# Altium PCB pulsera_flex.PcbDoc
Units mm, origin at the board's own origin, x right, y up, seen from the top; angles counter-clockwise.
Board outline 66.17 x 33.66 mm, 2 copper layers (Top Layer, Bottom Layer); 22 components, 13 nets, 52 pads, 0 vias.
Unrouted connection lines stored in the file: 4.
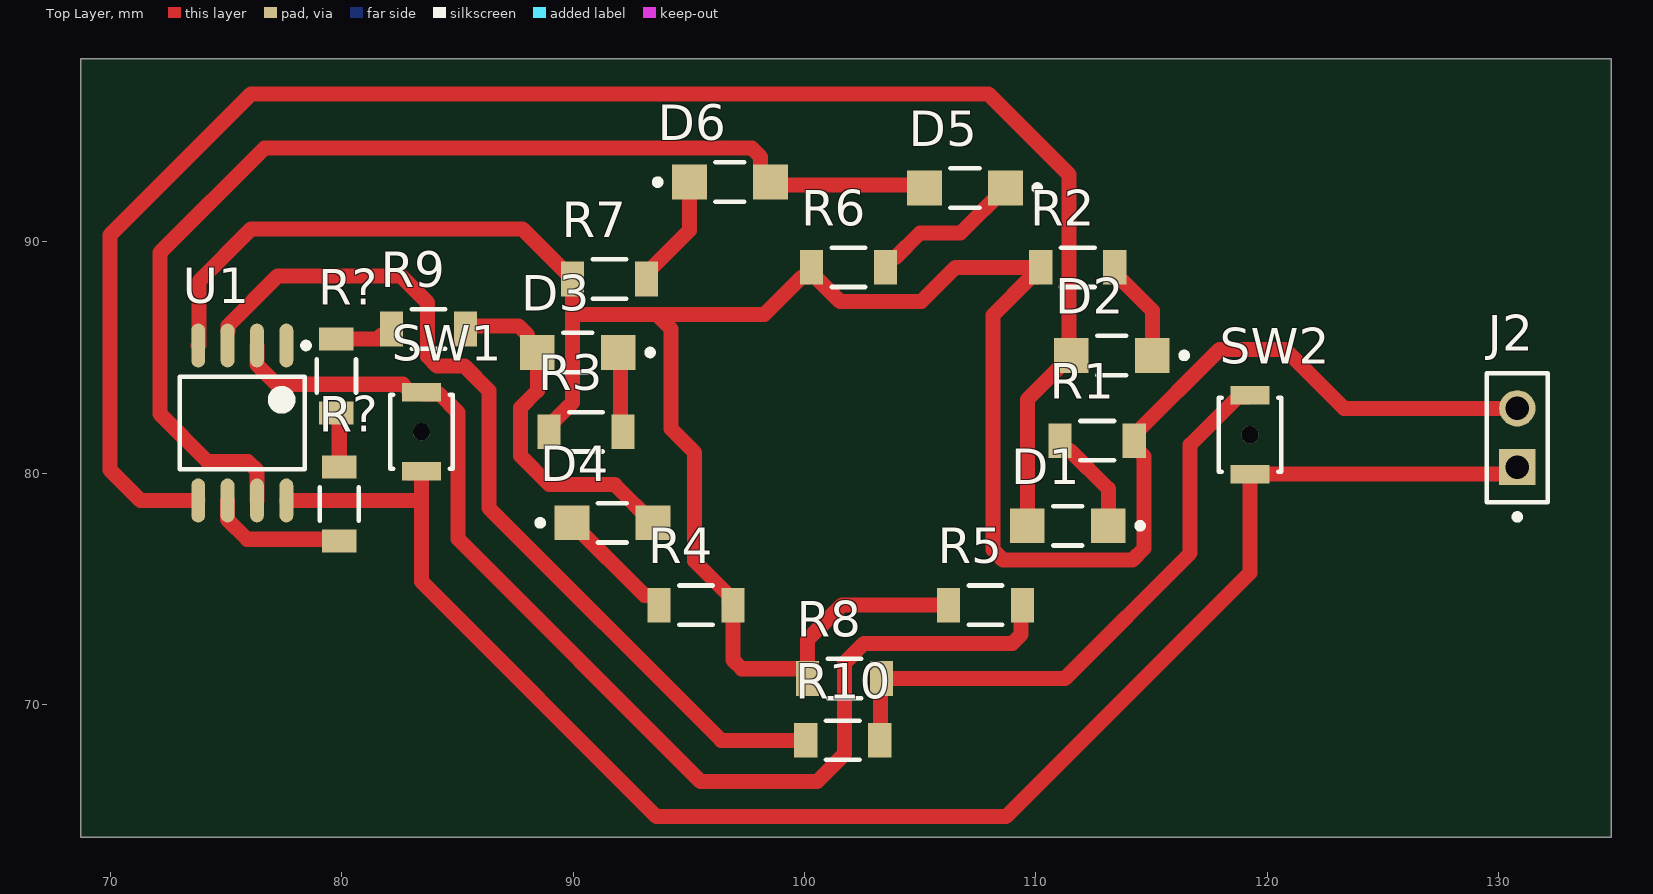
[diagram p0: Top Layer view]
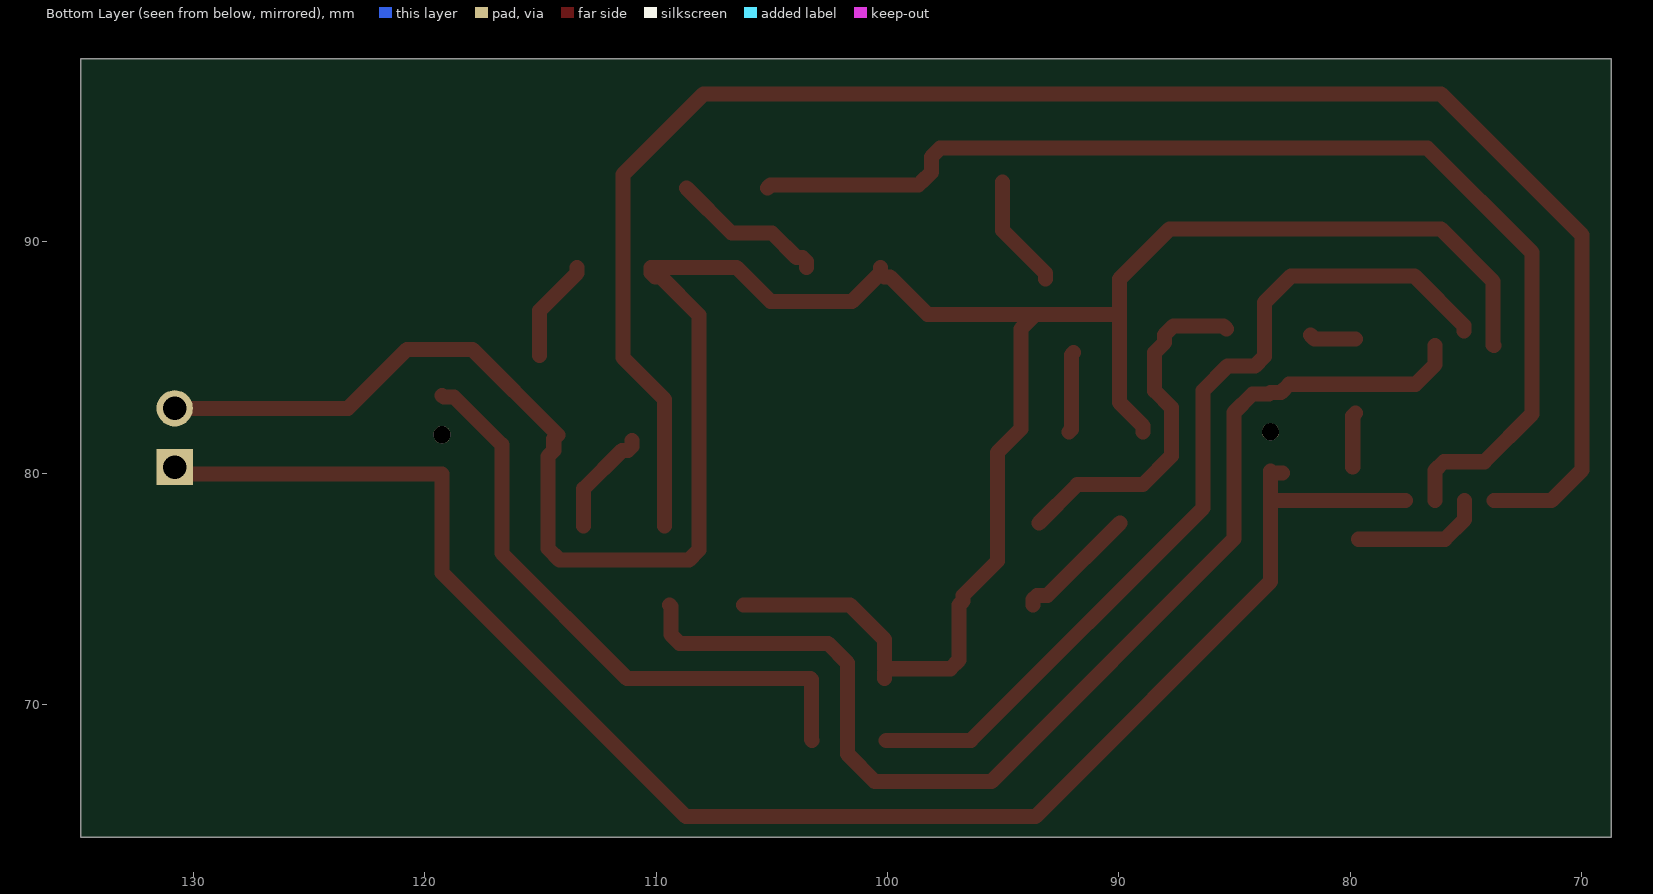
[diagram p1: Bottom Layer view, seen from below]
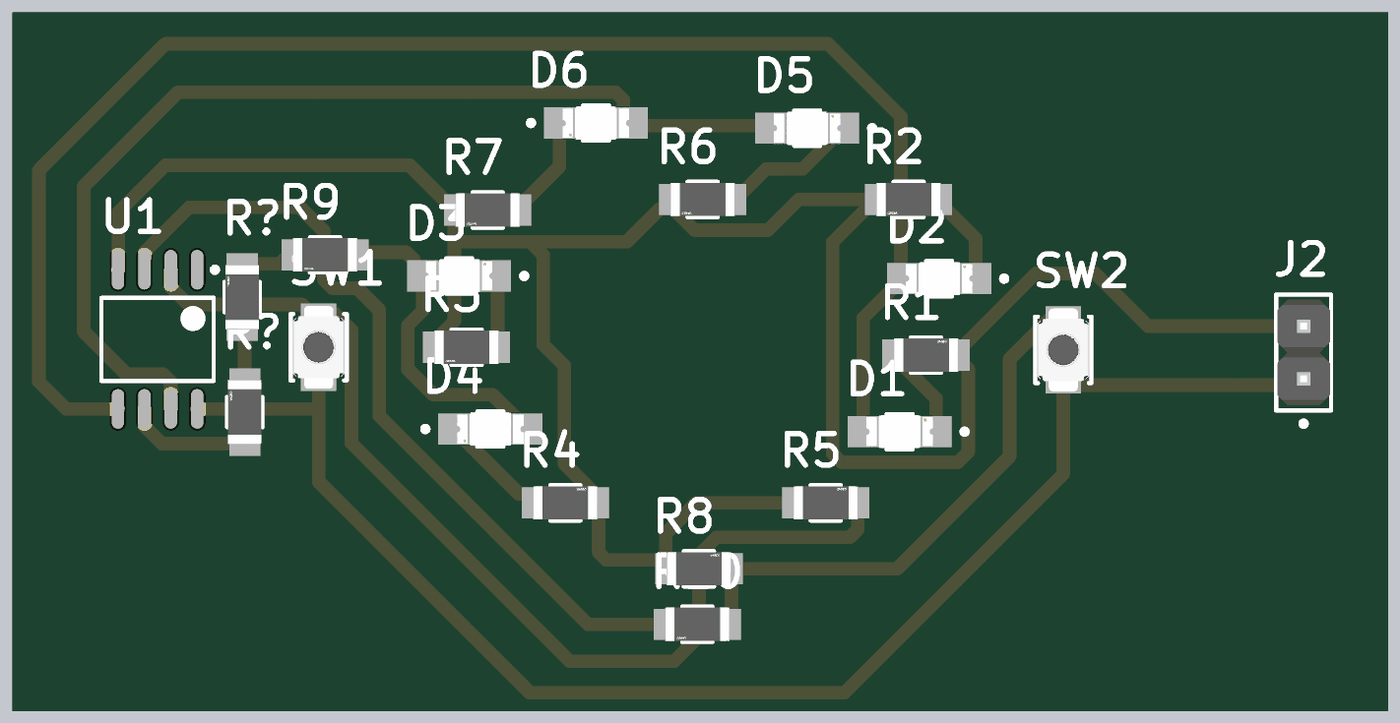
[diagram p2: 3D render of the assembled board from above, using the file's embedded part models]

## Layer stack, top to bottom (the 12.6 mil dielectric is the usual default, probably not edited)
Top Solder: solder mask 0.0102, Solder Resist, Dk 3.5
Top Layer: signal copper 0.0356
Dielectric 1: dielectric 0.32, FR-4, Dk 4.8
Bottom Layer: signal copper 0.0356
Bottom Solder: solder mask 0.0102, Solder Resist, Dk 3.5

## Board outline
68.707,64.262 134.874,64.262 134.874,97.917 68.707,97.917

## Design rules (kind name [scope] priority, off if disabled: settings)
Clearance [All] p1: gap=0.4 ignorepadtopadclearanceinfootprint=FALSE
PolygonConnect [All] p1: connectstyle=Relief reliefconductorwidth=0.254 reliefentries=4 polygonreliefangle="90 Angle" airgapwidth=0.254
RoutingVias [All] p1: holewidth=0.711 width=1.27 viastyle="Through Hole" minholewidth=0.711 minwidth=1.27 maxholewidth=0.711 maxwidth=1.27
SolderMaskExpansion [All] p1: expansion=0.102 istentingtop=FALSE
SupplyNets "Schematic Supply Nets_1" [InNet('GND')] p1: voltage=0.000
SupplyNets "Schematic Supply Nets" [InNet('VCC')] p2: voltage=0.000
Width [All] p1: maxlimit=0.65 minlimit=0.65 preferedwidth=0.65 minimp=50.000000 maximp=50.000000 favimp=50.000000
30 further rules are at their usual default settings.

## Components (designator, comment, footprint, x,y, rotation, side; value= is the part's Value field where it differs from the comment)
D1 "HSMS-C150" FP-HSMS-C150-MFG 111.379,77.724 r180 top
D2 "HSMS-C150" FP-HSMS-C150-MFG 113.284,85.09 r180 top
D3 "HSMS-C150" FP-HSMS-C150-MFG 90.198,85.217 r180 top
D4 "HSMS-C150" FP-HSMS-C150-MFG 91.694,77.851 r0 top
D5 "HSMS-C150" FP-HSMS-C150-MFG 106.934,92.329 r180 top
D6 "HSMS-C150" FP-HSMS-C150-MFG 96.774,92.583 r0 top
J2 "M20-9990246" FP-M20-9990246-MFG 130.81,81.534 r90 top
R1 "RC1206JR-070RL" FP-RC1206-MFG 112.649,81.407 r0 top value=0Ω
R2 "RC1206JR-070RL" FP-RC1206-MFG 111.811,88.9 r180 top value=0Ω
R3 "RC1206JR-070RL" FP-RC1206-MFG 90.551,81.788 r180 top value=0Ω
R4 "RC1206JR-070RL" FP-RC1206-MFG 95.301,74.295 r0 top value=0Ω
R5 "RC1206JR-070RL" FP-RC1206-MFG 107.823,74.295 r0 top value=0Ω
R6 "RC1206JR-070RL" FP-RC1206-MFG 101.905,88.9 r180 top value=0Ω
R7 "RC1206JR-070RL" FP-RC1206-MFG 91.567,88.392 r180 top value=0Ω
R8 "RC1206JR-070RL" FP-RC1206-MFG 101.727,71.12 r0 top value=0Ω
R9 "RC1206JR-070RL" FP-RC1206-MFG 83.744,86.233 r180 top value=0Ω
R10 "RC1206JR-070RL" FP-RC1206-MFG 101.651,68.453 r180 top value=0Ω
R? "RC1206JR-070RL" FP-RC1206-MFG 79.756,84.201 r90 top value=0Ω
R? "RC1206JR-070RL" FP-RC1206-MFG 79.883,78.664 r90 top value=0Ω
SW1 "B3U-1000P-B" FP-B3U-1000P-B-MFG 83.439,81.788 r90 top
SW2 "B3U-1000P-B" FP-B3U-1000P-B-MFG 119.253,81.661 r90 top
U1 "ATtiny45-20SUR" 8S2_L 75.692,82.169 r270 top

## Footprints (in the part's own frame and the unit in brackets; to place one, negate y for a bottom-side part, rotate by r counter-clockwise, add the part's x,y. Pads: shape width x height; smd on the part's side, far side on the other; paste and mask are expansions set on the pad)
8S2_L [mm] "SOP, 8-Leads, Body 5.3x5.3mm, Pitch 1.27mm, IPC High Density"
  oval 1.9x0.6 smd: 1(-3.35,1.905) 2(-3.35,0.635) 3(-3.35,-0.635) 4(-3.35,-1.905) 5(3.35,-1.905) 6(3.35,-0.635) 7(3.35,0.635) 8(3.35,1.905)
  silkscreen extent -3.47,-2.7 2,2.88, body extent -2.7,-2.68 2.7,2.68, height 2.16
FP-B3U-1000P-B-MFG [mm]
  rect 0.8x1.7 smd paste+0 mask+0: 1(-1.7,0) 2(1.7,0)
  round 0.75 hole 0.75 unplated paste-2539.97 mask+0: ""(0,0)
  silkscreen extent -1.6,-1.35 1.6,1.35, body extent -2.2,-1.45 2.2,1.45, height 0.25
FP-HSMS-C150-MFG [mm]
  rect 1.5x1.5 smd paste+0 mask+0: 1(-1.75,0) 2(1.75,0)
  silkscreen extent -3.25,-0.85 0.63,0.85, body extent -2.6,-0.95 2.6,0.95, height 0.25
FP-M20-9990246-MFG [mm]
  rect 1.57x1.57 hole 1.02 paste-2539.97 mask+0: 1(-1.27,0)
  round 1.57 hole 1.02 paste-2539.97 mask+0: 2(1.27,0)
  silkscreen extent -3.55,-1.32 2.79,1.32, body extent -2.89,-1.42 2.89,1.42, height 0.25
FP-RC1206-MFG [mm]
  rect 1x1.5 smd paste+0 mask+0: 1(-1.6,0) 2(1.6,0)
  silkscreen extent -0.72,-0.85 0.72,0.85, body extent -2.2,-0.95 2.2,0.95, height 0.25

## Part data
D1 D2 D3 D4 D5 D6: library part CMP-21615-000001-1, "LED RED DIFFUSED CHIP SMD", Case Code (Imperial)=1206, Case Code (Metric)=3216, Color=Red, Forward Current=20mA, Forward Voltage=2.1V, Lens Color=White, Max Operating Temperature=85°C, Min Operating Temperature=-40°C, Package Quantity=1, Power Dissipation=65mW, Reverse Voltage=5V
J2: library part CMP-15831-000009-1, "CONN HEADER VERT 2POS 2.54MM", Current Rating=3A, Manufacturer=Harwin, Temperature="-40°C to +105°C", Temperature Range High=+105°C, Temperature Range Low=-40°C
R1 R2 R3 R4 R5 R6 R7 R8 R9 R10 R? R?: library part CMP-2100-03681-2, "RES SMD 0 OHM JUMPER 1/4W 1206", Manufacturer=YAGEO, Package=RC1206, Power Rating=0.25W, Resistance=0Ω, Temperature="-55°C to +155°C", Temperature Coefficient=300ppm/°C, Temperature Range High=+155°C, Temperature Range Low=-55°C, Tolerance=5%, Voltage Rating=200V
SW1 SW2: library part CMP-08834-000005-1, "SWITCH TACTILE SPST-NO 0.05A 12V", Ambient Temperature Range High=+70°C, Ambient Temperature Range Low=-25°C, Contact Current Rating=50mA, Contact Resistance=100mΩ, Manufacturer=Omron, Operating Force=1.5N, Package=0, Temperature="-25°C to +70°C", Voltage Rating Dc=12V
U1: library part CMP-0093-00355-1, "8-bit AVR Microcontroller, 20MHz, 2.7-5.5V, 4K Flash, 256 Bytes EEPROM, 256 Bytes SRAM, Industrial Grade (-40°C to 85°C), 8-Lead SOIC, Pb-Free, Reel"

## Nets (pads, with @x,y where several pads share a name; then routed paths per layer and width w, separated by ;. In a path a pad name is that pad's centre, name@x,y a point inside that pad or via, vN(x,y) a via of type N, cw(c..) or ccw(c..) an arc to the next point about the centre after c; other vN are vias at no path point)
BOTON1: R5.2 SW1.2 U1.2 | length 50.8
  Top Layer w0.65: U1.2 76.327,84.689 77.172,83.844 82.633,83.844 82.989,83.488 SW1.2 83.514,83.413 84.227,83.413 85.014,82.626 85.014,77.165 95.504,66.675 100.548,66.675 101.727,67.854 101.727,71.795 102.574,72.643 108.985,72.643 109.366,73.024 109.366,74.238 R5.2
BOTON2: R8.2 R10.1 R10.2 SW2.2 U1.3 | length 65.2
  Top Layer w0.65: U1.3@75.082,86.144 75.082,86.385 77.216,88.519 82.55,88.519 83.693,87.376 83.693,85.05 84.112,84.631 85.295,84.631 86.36,83.566 86.36,78.486 96.393,68.453 R10.2 ; R10.1 103.289,68.491 103.289,71.082 R8.2 111.252,71.12 116.671,76.539 116.671,81.229 118.728,83.286 119.178,83.286 SW2.2
GND: J2.2 R1.2 R2.2 R3.2 R4.2 R5.1 R6.2 R7.2 R8.1 U1.4 | length 122.5
  Top Layer w0.65: U1.4 73.812,85.544 73.812,88.29 76.073,90.551 87.808,90.551 R7.2 89.967,86.868 ; R3.2 88.951,82.038 89.967,83.054 89.967,86.868 ; R8.1 100.127,71.37 99.952,71.545 97.282,71.545 96.901,71.926 R4.2 96.726,74.47 96.726,74.72 95.25,76.196 95.25,80.899 94.234,81.915 94.234,86.233 93.599,86.868 ; R8.1@100.127,71.545 100.127,72.812 101.613,74.298 106.048,74.298 106.051,74.295 R5.1 ; R6.2 R6.2@100.305,88.65 ; J2.2 123.317,82.804 120.777,85.344 117.936,85.344 114.249,81.657 114.424,81.482 114.424,80.982 114.681,80.725 114.681,76.751 114.179,76.249 108.579,76.249 108.154,76.674 108.154,86.843 109.786,88.475 110.036,88.475 110.211,88.65 R2.2 106.521,88.9 105.046,87.425 101.53,87.425 R6.2@100.305,88.65 ; 89.967,86.868 93.599,86.868 ; 93.599,86.868 98.273,86.868 99.88,88.475 100.13,88.475 R6.2@100.305,88.65
LED1: D1.2 D2.2 U1.5 | length 75.9
  Top Layer w0.65: U1.5 71.295,78.819 69.977,80.137 69.977,90.297 76.073,96.393 107.95,96.393 111.436,92.907 111.436,84.992 109.629,83.185 D1.2
LED2: D3.2 D4.2 R9.1 R9.2 R?.1 R?.2 U1.6 | length 25.7
  Top Layer w0.65: U1.6 75.057,77.989 75.902,77.144 R?.1@79.629,77.144 ; R?.1@79.756,82.601 79.883,82.474 R?.2@79.883,80.264 ; R?.2@79.756,85.801 81.537,85.801 R9.2@81.712,85.976 ; R9.1 85.471,86.36 87.642,86.36 88.023,85.979 88.023,85.642 D3.2 88.448,83.56 87.726,82.838 87.726,80.738 88.962,79.502 91.793,79.502 D4.2
LED3: D5.2 D6.2 U1.7 | length 49.3
  Top Layer w0.65: U1.7 76.327,80.113 75.946,80.494 74.197,80.494 72.136,82.555 72.136,89.535 76.659,94.058 97.718,94.058 98.099,93.677 98.099,93.008 D6.2 ; D6.2@98.651,92.456 105.057,92.456 D5.2
NetD1_1: D1.1 R1.1 | length 4.7
  Top Layer w0.65: R1.1 111.049,81.157 111.224,80.982 111.474,80.982 113.129,79.327 D1.1
NetD2_1: D2.1 R2.1 | length 4.5
  Top Layer w0.65: R2.1 113.411,88.65 115.034,87.027 D2.1
NetD3_1: D3.1 R3.1 | length 3.5
  Top Layer w0.65: D3.1 92.05,85.115 92.05,81.889 R3.1
NetD4_1: D4.1 R4.1 | length 5.4
  Top Layer w0.65: D4.1 93.075,74.72 93.526,74.72 93.701,74.545 R4.1
NetD5_1: D5.1 R6.1 | length 6.7
  Top Layer w0.65: R6.1 103.505,89.15 103.68,89.325 103.93,89.325 104.98,90.375 106.73,90.375 D5.1
NetD6_1: D6.1 R7.1 | length 5
  Top Layer w0.65: R7.1 93.167,88.642 95.024,90.499 D6.1
VCC: J2.1 SW1.1 SW2.1 U1.8 | length 71.5
  Top Layer w0.65: U1.8 79.211,78.819 79.214,78.822 83.394,78.822 83.439,78.867 ; SW1.1@82.914,80.013 83.364,80.013 SW1.1 83.439,78.867 ; J2.1 130.507,79.961 SW2.1 119.253,75.692 108.712,65.151 93.599,65.151 83.439,75.311 83.439,78.867
pads on no net: SW1. SW2. U1.1

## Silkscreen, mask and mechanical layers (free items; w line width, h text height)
Mechanical 1:
  lines w0.254: 68.707,64.262 68.707,97.917 134.874,97.917 134.874,64.262 68.707,64.262 ; 68.707,64.262 68.707,64.262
